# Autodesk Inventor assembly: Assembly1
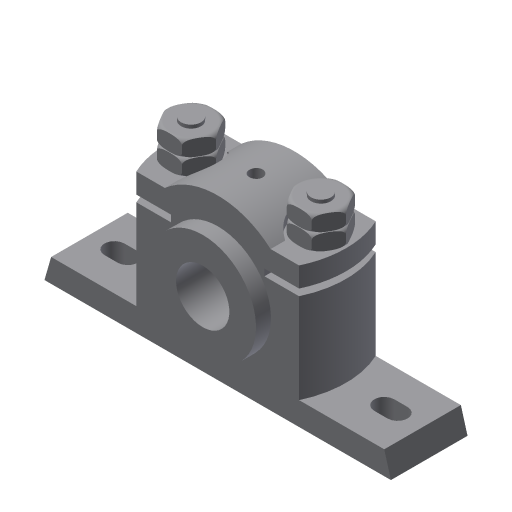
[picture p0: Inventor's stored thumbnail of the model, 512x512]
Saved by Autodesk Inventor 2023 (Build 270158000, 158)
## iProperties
Created: 2016-03
Part Number: Assembly1
Document SubType Name: Assembly
Designer: Sandeep
Author: Sandeep
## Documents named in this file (7)
- D:\PROJECTS\Project 2022\Autodesk Inventor For Professional 2023\RESOURCES INVENTOR 2023\RESOURCES INVENTOR 2023\Inventor_2023_tut\Inventor_2023_tut\c13_Inv_2023_tut\c13_Inv_tut_2023\c13-tut01-inv\Plummer block\Assembly1.iam
- D:\PROJECTS\Project 2022\Autodesk Inventor For Professional 2023\RESOURCES INVENTOR 2023\RESOURCES INVENTOR 2023\Inventor_2023_tut\Inventor_2023_tut\c13_Inv_2023_tut\c13_Inv_tut_2023\c13-tut01-inv\Plummer block\Casting.ipt
- D:\PROJECTS\Project 2022\Autodesk Inventor For Professional 2023\RESOURCES INVENTOR 2023\RESOURCES INVENTOR 2023\Inventor_2023_tut\Inventor_2023_tut\c13_Inv_2023_tut\c13_Inv_tut_2023\c13-tut01-inv\Plummer block\Brasses.ipt
- D:\PROJECTS\Project 2022\Autodesk Inventor For Professional 2023\RESOURCES INVENTOR 2023\RESOURCES INVENTOR 2023\Inventor_2023_tut\Inventor_2023_tut\c13_Inv_2023_tut\c13_Inv_tut_2023\c13-tut01-inv\Plummer block\Cap.ipt
- D:\PROJECTS\Project 2022\Autodesk Inventor For Professional 2023\RESOURCES INVENTOR 2023\RESOURCES INVENTOR 2023\Inventor_2023_tut\Inventor_2023_tut\c13_Inv_2023_tut\c13_Inv_tut_2023\c13-tut01-inv\Plummer block\Bolt.ipt
- D:\PROJECTS\Project 2022\Autodesk Inventor For Professional 2023\RESOURCES INVENTOR 2023\RESOURCES INVENTOR 2023\Inventor_2023_tut\Inventor_2023_tut\c13_Inv_2023_tut\c13_Inv_tut_2023\c13-tut01-inv\Plummer block\Nut.ipt
- D:\PROJECTS\Project 2022\Autodesk Inventor For Professional 2023\RESOURCES INVENTOR 2023\RESOURCES INVENTOR 2023\Inventor_2023_tut\Inventor_2023_tut\c13_Inv_2023_tut\c13_Inv_tut_2023\c13-tut01-inv\Plummer block\Lock Nut.ipt
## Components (9 placed, 6 different names)
1. Casting:1 — Mate:1, Mate:2, Insert:1, Insert:2, Angle:1, Angle:2
2. Brasses:1 — Mate:1, Mate:2, Mate:3, Mate:4
3. Cap:1 — Mate:3, Mate:4, Insert:3, Insert:5
4. Bolt:1 — Insert:1, Angle:1
5. Bolt:2 — Insert:2, Angle:2
6. Nut:1 — Insert:3, Insert:4
7. Nut:2 — Insert:5, Insert:6
8. Lock Nut:1 — Insert:4
9. Lock Nut:2 — Insert:6
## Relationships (12: Insert 6, Mate 4, Angle 2)
- Mate:1: Casting:1 ↔ Brasses:1
- Mate:2: Casting:1 ↔ Brasses:1
- Mate:3: Brasses:1 ↔ Cap:1
- Mate:4: Brasses:1 ↔ Cap:1
- Insert:1: Casting:1 ↔ Bolt:1
- Insert:2: Casting:1 ↔ Bolt:2
- Angle:1: Casting:1 ↔ Bolt:1
- Angle:2: Casting:1 ↔ Bolt:2
- Insert:3: Cap:1 ↔ Nut:1
- Insert:4: Nut:1 ↔ Lock Nut:1
- Insert:5: Cap:1 ↔ Nut:2
- Insert:6: Nut:2 ↔ Lock Nut:2
